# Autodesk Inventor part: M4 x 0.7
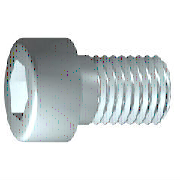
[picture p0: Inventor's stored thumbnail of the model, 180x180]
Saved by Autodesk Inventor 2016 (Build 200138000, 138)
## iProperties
IsCustomPart: 0
Created: 2015-10
Part Number: M4 x 0.7
Material: 강, 연강
Description: 6각머리 태핑 나사
Document SubType Name: Modeling
Standard: KS B 1003
Designer: mdu
Standards Organization: KS
Language: ko-KR
Size Designation: M 4 x 25
Categories: <MemberInstance><Categories><Category DisplayName="조임쇠" InternalName="e4da775c-781d-43d5-af7c-5136215cf5a6" Mnemonic="FSTN"><Category DisplayName="볼트" InternalN
Density: 1 g/cm^3
Appearance: 강철
Author: mdu
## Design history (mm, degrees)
sketch "스케치1"
  geometry: L1 (-1, 0)-(25, 0); L2 (25, 0)-(25, 2); L3 (25, 2)-(1.75, 2); L4 (1.75, 2)-(1.32, 2); L5 (1.32, 2)-(0, 2); L6 (0, 2)-(0, 3.5); L7 (0, 3.5)-(-4, 3.5); L8 (-4, 3.5)-(-4, 1.732); L9 (-4, 1.732)-(-2, 1.732); L10 (-2, 1.732)-(-1, 0); L11 (-9.8, 0)-(30.8, 0) reference; L12 (0, -0.7)-(0, 4.2) reference; L13 (1.75, 2)-(0, 2)
  constraints: 22 end point, 6 parallel, 2 collinear, 2 perpendicular, 1 horizontal, 1 point on line
  dimensions: "d1" = 23.25 distance from line of L3.end L2 (= GEL); "d2" = 0.42952 distance of L4.end L3.end (computed from GAL); "d3" = 4 distance between parallel lines of L8 L6 (= KOH); "d4" = 2 distance of L8.end L9.end (= INTI); "d5" = 60 deg angle of L10 L1; "d6" = 4 diameter of L3 L1 (= GD); "d7" = 4 diameter of L5 L1 (= BDM); "d8" = 3.4641 diameter of L9 L1 (= 1.1547 x SW); "d9" = 7 diameter of L7 L1 (= KOD); "d26" = 25 distance between parallel lines of L12 L2 (= NLG)
revolve "본체" sketch "스케치1" stored, may be unused: angle "d10" = 90 deg
sketch "스케치2"
  geometry: L1 (0, -4.9)-(0, 4.9) reference; L2 (-4.9, 0)-(4.9, 0) reference; L3 (1.732, 0)-(0.866, -1.5); L4 (0.866, -1.5)-(-0.866, -1.5); L5 (-0.866, -1.5)-(-1.732, 0); L6 (-1.732, 0)-(-0.866, 1.5); L7 (-0.866, 1.5)-(0.866, 1.5); L8 (0.866, 1.5)-(1.732, 0); 2 further points
  constraints: 12 end point, 1 coincident, 1 horizontal alignment, 1 point on line, 12 other
extrude "슬롯" join sketch "스케치2" stored distance "d11" = 10; taper "d12" = 0 deg
workplane "Work Plane1"
fillet "Fillet2" dims "d30" = 0.1 (= R)
body "Solid1"
fillet "모깎기1" dims "d17" = 0.4 (= RR)
feature "스레드" dims "d13" = 23.25 (= GEL), "d14" = 0
chamfer "모따기1" distance "d15" = 0.42941 (= -0.5 x SPD + 0.5 x GD); stored, may be unused: second distance "d16" = 0.42941 (= GUL), angle "d27" = 45 deg
other parameters: "GD" = 4 (= NND) [user parameter; used in 2 equation terms], "NLG" = 25 [user parameter; used in 1 equation term], "GEL" = 23.25 [user parameter; used in 2 equation terms], "KOD" = 7 [user parameter; used in 1 equation term], "KOH" = 4 [user parameter; used in 1 equation term], "INTI" = 2 [user parameter; used in 1 equation term], "GAL" = 0.42941 (= 0.61345 x PTC) [user parameter; used in 1 equation term], "GUL" = 0.42941 (= 0.61345 x PTC) [user parameter; used in 1 equation term], "BDM" = 4 (= NND) [user parameter; used in 1 equation term], "SW" = 3 [user parameter; used in 2 equation terms], "RR" = 0.4 [user parameter; used in 1 equation term], "SPD" = 3.14117 (= NND - 1.2269 x PTC) [user parameter; used in 1 equation term], "d19" = 0, "d28" = 0, "d29" = 0, "R" = 0.1 [user parameter; used in 1 equation term], "PHH" = 0.2 [user parameter], "GD1" = 3.14117 (= THREADDIA - 1.2269 x PTC) [user parameter], "THREADDIA" = 4 [user parameter; used in 1 equation term], "FAWI" = 45 deg [user parameter], "TPU" = 14.28571 (computed from PTC) [user parameter], "PTC" = 0.7 [user parameter; used in 5 equation terms], "NND" = 4 [user parameter; used in 3 equation terms], "TOA" = 30 deg [user parameter], "E0" = 3.465 (= 1.155 x SW) [user parameter]
